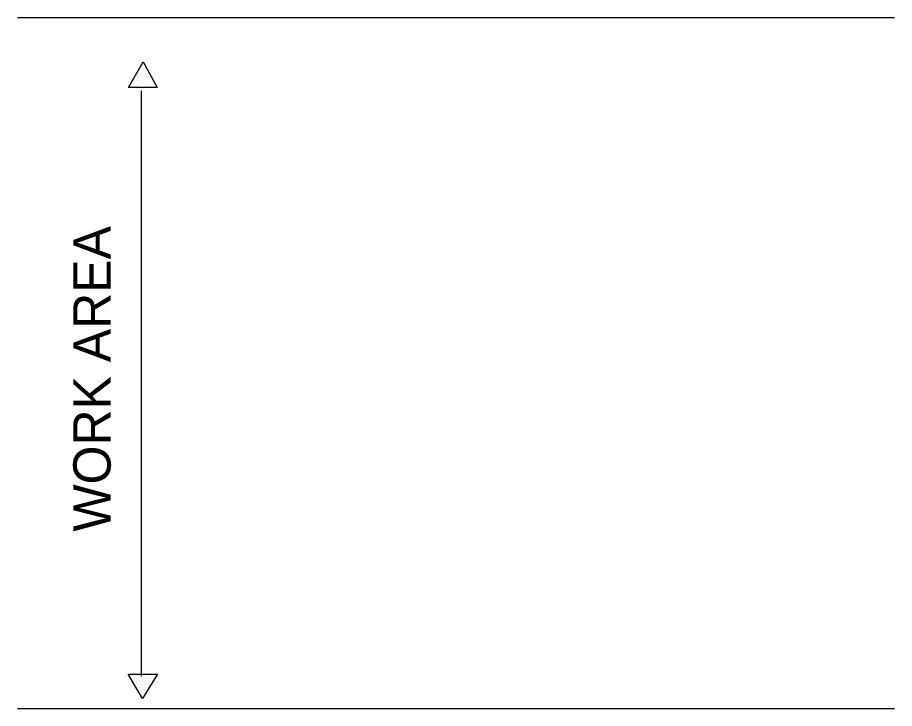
# Model space of a CAD drawing. Extents: x 610.92 to 617.75, y 610.91 to 620.34.
# Drawn here: x 614.338 to 615.746, y 614.928 to 616.037 of the extents above; entities that cross this region are included whole.
import ezdxf

# ---------------------------------------------------------------- set-up
doc = ezdxf.new("R2010")
doc.units = 0
doc.layers.add('DETL-DIMS', color=7, linetype='Continuous')
doc.layers.add('DETL-NOTE', color=7, linetype='Continuous')

msp = doc.modelspace()

# ---------------------------------------------------------------- linework, layer by layer
at = {"layer": 'DETL-DIMS'}
for p, q in [((614.3382, 616.0372), (615.7462, 616.0372)), ((614.5166, 615.926), (614.5398, 615.966)), ((614.5366, 615.958), (614.5366, 615.958)), ((614.539, 615.962), (614.539, 615.962)), ((614.5398, 615.966), (614.5622, 615.9252)), ((614.5286, 615.9444), (614.5286, 615.9444)), ((614.531, 615.9484), (614.531, 615.9484)), ((614.5342, 615.9532), (614.5342, 615.9532)), ((614.5374, 615.9476), (614.5374, 615.9476)), ((614.5406, 615.9524), (614.5406, 615.9524)), ((614.543, 615.9572), (614.543, 615.9572)), ((614.543, 615.9476), (614.543, 615.9476)), ((614.5454, 615.9524), (614.5454, 615.9524)), ((614.5486, 615.9476), (614.5486, 615.9476)), ((614.5214, 615.9316), (614.5214, 615.9316)), ((614.5238, 615.9356), (614.5238, 615.9356)), ((614.5262, 615.9404), (614.5262, 615.9404)), ((614.527, 615.9308), (614.527, 615.9308)), ((614.5302, 615.9356), (614.5302, 615.9356)), ((614.5326, 615.9396), (614.5326, 615.9396)), ((614.5326, 615.93), (614.5326, 615.93)), ((614.535, 615.9436), (614.535, 615.9436)), ((614.5358, 615.9348), (614.5358, 615.9348)), ((614.5382, 615.9396), (614.5382, 615.9396)), ((614.5382, 615.9308), (614.5382, 615.9308)), ((614.5406, 615.9436), (614.5406, 615.9436)), ((614.5406, 615.9348), (614.5406, 615.9348)), ((614.543, 615.9388), (614.543, 615.9388)), ((614.5438, 615.93), (614.5438, 615.93)), ((614.5454, 615.9428), (614.5454, 615.9428)), ((614.5462, 615.934), (614.5462, 615.934)), ((614.5486, 615.9388), (614.5486, 615.9388)), ((614.551, 615.9428), (614.551, 615.9428)), ((614.5518, 615.9332), (614.5518, 615.9332)), ((614.555, 615.938), (614.555, 615.938)), ((614.5622, 615.9252), (614.5158, 615.9252)), ((614.5158, 615.9252), (614.5158, 615.9252)), ((614.519, 615.9276), (614.519, 615.9276)), ((614.5246, 615.9268), (614.5246, 615.9268)), ((614.5302, 615.926), (614.5302, 615.926)), ((614.5358, 615.926), (614.5358, 615.926)), ((614.5374, 614.9804), (614.5374, 615.9196)), ((614.5414, 615.926), (614.5414, 615.926)), ((614.547, 615.9252), (614.547, 615.9252)), ((614.5494, 615.9292), (614.5494, 615.9292)), ((614.555, 615.9292), (614.555, 615.9292)), ((614.5158, 614.9836), (614.5158, 614.9836)), ((614.539, 614.9444), (614.5158, 614.9836)), ((614.5166, 614.9836), (614.563, 614.9836)), ((614.519, 614.9828), (614.519, 614.9828)), ((614.5214, 614.9772), (614.5214, 614.9772)), ((614.5238, 614.9828), (614.5238, 614.9828)), ((614.5238, 614.9724), (614.5238, 614.9724)), ((614.5262, 614.9772), (614.5262, 614.9772)), ((614.5286, 614.9828), (614.5286, 614.9828)), ((614.5286, 614.9724), (614.5286, 614.9724)), ((614.5318, 614.9772), (614.5318, 614.9772)), ((614.5342, 614.9828), (614.5342, 614.9828)), ((614.5342, 614.9724), (614.5342, 614.9724)), ((614.5366, 614.9772), (614.5366, 614.9772)), ((614.563, 614.9836), (614.539, 614.9444)), ((614.539, 614.9828), (614.539, 614.9828)), ((614.539, 614.9724), (614.539, 614.9724)), ((614.5414, 614.9772), (614.5414, 614.9772)), ((614.5438, 614.9828), (614.5438, 614.9828)), ((614.5438, 614.9724), (614.5438, 614.9724)), ((614.5462, 614.9772), (614.5462, 614.9772)), ((614.5486, 614.9828), (614.5486, 614.9828)), ((614.5486, 614.9724), (614.5486, 614.9724)), ((614.5518, 614.9772), (614.5518, 614.9772)), ((614.5542, 614.9828), (614.5542, 614.9828)), ((614.5542, 614.9724), (614.5542, 614.9724)), ((614.5566, 614.9772), (614.5566, 614.9772)), ((614.559, 614.9828), (614.559, 614.9828)), ((614.5262, 614.9676), (614.5262, 614.9676)), ((614.5294, 614.9628), (614.5294, 614.9628)), ((614.5318, 614.9676), (614.5318, 614.9676)), ((614.5342, 614.9628), (614.5342, 614.9628)), ((614.5366, 614.9676), (614.5366, 614.9676)), ((614.539, 614.9628), (614.539, 614.9628)), ((614.5414, 614.9676), (614.5414, 614.9676)), ((614.5438, 614.9628), (614.5438, 614.9628)), ((614.5462, 614.9676), (614.5462, 614.9676)), ((614.5486, 614.9628), (614.5486, 614.9628)), ((614.5518, 614.9676), (614.5518, 614.9676)), ((614.5318, 614.9572), (614.5318, 614.9572)), ((614.5366, 614.9572), (614.5366, 614.9572)), ((614.539, 614.9524), (614.539, 614.9524)), ((614.5414, 614.9572), (614.5414, 614.9572)), ((614.5462, 614.9572), (614.5462, 614.9572)), ((614.3382, 614.9284), (615.7462, 614.9284))]:
    msp.add_line(p, q, dxfattribs=at)

# ---------------------------------------------------------------- texts
at = {"layer": 'DETL-NOTE'}
msp.add_text('WORK AREA', height=0.06, rotation=90, dxfattribs=at).set_placement((614.4877, 615.2122))

doc.saveas('drawing.dxf')
